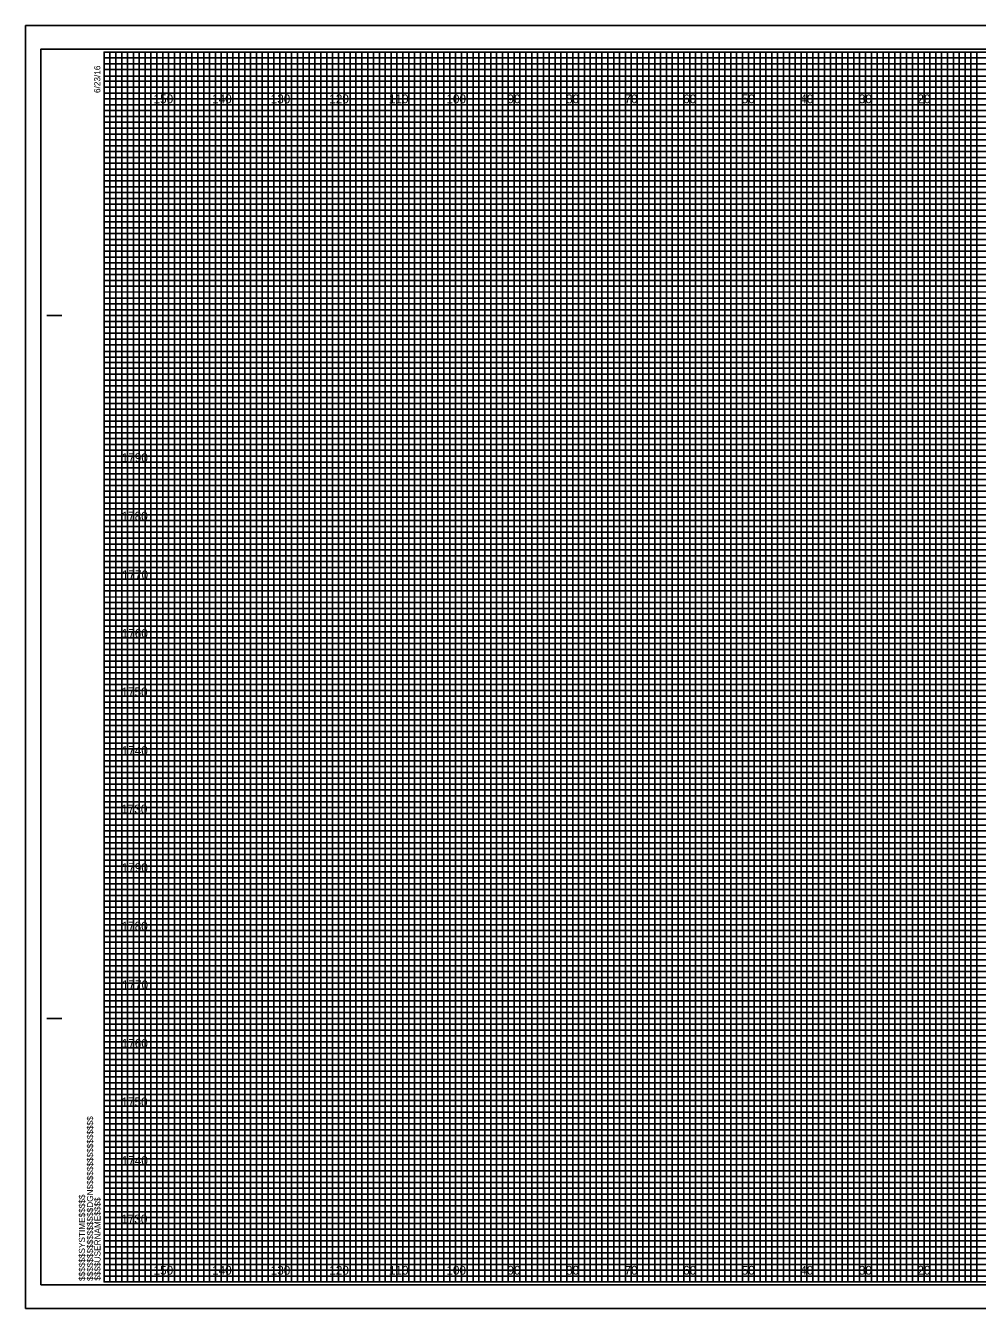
# Model space of a CAD drawing. Extents: x -15 to 323, y -5 to 6170.
# Drawn here: x -13.4 to 149.1, y 3955.5 to 4174.5 of the extents above; entities that cross this region are included whole.
import ezdxf

# ---------------------------------------------------------------- set-up
doc = ezdxf.new("R2010")
doc.units = 0
for name, color, linetype in [('Prop XS DDE', 7, 'Continuous'), ('Prop XS DDE Slope Text', 7, 'Continuous'), ('Prop XS DDE Text', 7, 'Continuous'), ('Prop XS Earthwork Shape', 7, 'Continuous'), ('Prop XS Noise Wall', 7, 'Continuous'), ('Prop XS Retaining Wall', 7, 'Continuous'), ('Prop XS Station Labels', 7, 'Continuous'), ('Scratch_Level_3', 7, 'Continuous'), ('Scratch_Level_7', 7, 'Continuous'), ('Scratch_Level_8', 7, 'Continuous'), ('Sheet Cross Section Grid Minor 1 CELL', 7, 'Continuous')]:
    doc.layers.add(name, color=color, linetype=linetype)

msp = doc.modelspace()

# ---------------------------------------------------------------- linework, layer by layer
at = {"layer": 'Prop XS DDE'}
msp.add_lwpolyline([(-13.4, 3955.5), (323.3, 3955.5), (323.3, 4174.5), (-13.4, 4174.5)], close=True, dxfattribs=at)
at = {"layer": 'Prop XS DDE Slope Text'}
msp.add_lwpolyline([(-10.8, 3959.5), (322.4, 3959.5), (322.4, 4170.5), (-10.8, 4170.5)], close=True, dxfattribs=at)
at = {"layer": 'Prop XS DDE Text'}
for p, q in [((10, 3960), (10, 4170)), ((20, 3960), (20, 4170)), ((30, 3960), (30, 4170)), ((40, 3960), (40, 4170)), ((50, 3960), (50, 4170)), ((60, 3960), (60, 4170)), ((70, 3960), (70, 4170)), ((80, 3960), (80, 4170)), ((90, 3960), (90, 4170)), ((100, 3960), (100, 4170)), ((110, 3960), (110, 4170)), ((120, 3960), (120, 4170)), ((130, 3960), (130, 4170)), ((140, 3960), (140, 4170)), ((0, 4160), (320, 4160)), ((0, 4150), (320, 4150)), ((0, 4140), (320, 4140)), ((0, 4130), (320, 4130)), ((0, 4120), (320, 4120)), ((0, 4110), (320, 4110)), ((0, 4100), (320, 4100)), ((0, 4090), (320, 4090)), ((0, 4080), (320, 4080)), ((0, 4070), (320, 4070)), ((0, 4060), (320, 4060)), ((0, 4050), (320, 4050)), ((0, 4040), (320, 4040)), ((0, 4030), (320, 4030)), ((0, 4020), (320, 4020)), ((0, 4010), (320, 4010)), ((0, 4000), (320, 4000)), ((0, 3990), (320, 3990)), ((0, 3980), (320, 3980)), ((0, 3970), (320, 3970))]:
    msp.add_line(p, q, dxfattribs=at)
at = {"layer": 'Prop XS Earthwork Shape'}
for p, q in [((10, 4170), (0, 4170)), ((10, 3960), (10, 4170)), ((30, 4170), (20, 4170)), ((20, 4170), (20, 3960)), ((30, 3960), (30, 4170)), ((50, 4170), (40, 4170)), ((40, 4170), (40, 3960)), ((50, 3960), (50, 4170)), ((70, 4170), (60, 4170)), ((60, 4170), (60, 3960)), ((70, 3960), (70, 4170)), ((90, 4170), (80, 4170)), ((80, 4170), (80, 3960)), ((90, 3960), (90, 4170)), ((110, 4170), (100, 4170)), ((100, 4170), (100, 3960)), ((110, 3960), (110, 4170)), ((130, 4170), (120, 4170)), ((120, 4170), (120, 3960)), ((130, 3960), (130, 4170)), ((150, 4170), (140, 4170)), ((140, 4170), (140, 3960)), ((20, 3960), (10, 3960)), ((40, 3960), (30, 3960)), ((60, 3960), (50, 3960)), ((80, 3960), (70, 3960)), ((100, 3960), (90, 3960)), ((120, 3960), (110, 3960)), ((140, 3960), (130, 3960))]:
    msp.add_line(p, q, dxfattribs=at)
for points in [[(0, 4160), (320, 4160), (320, 4150), (0, 4150)], [(0, 4140), (320, 4140), (320, 4130), (0, 4130)], [(0, 4120), (320, 4120), (320, 4110), (0, 4110)], [(0, 4100), (320, 4100), (320, 4090), (0, 4090)], [(0, 4080), (320, 4080), (320, 4070), (0, 4070)], [(0, 4060), (320, 4060), (320, 4050), (0, 4050)], [(0, 4040), (320, 4040), (320, 4030), (0, 4030)], [(0, 4020), (320, 4020), (320, 4010), (0, 4010)], [(0, 4000), (320, 4000), (320, 3990), (0, 3990)], [(0, 3980), (320, 3980), (320, 3970), (0, 3970)]]:
    msp.add_lwpolyline(points, dxfattribs=at)
at = {"layer": 'Prop XS Noise Wall'}
for p, q in [((-9.8, 4125), (-7.3, 4125)), ((-9.7, 4125), (-7.2, 4125)), ((-9.8, 4005), (-7.3, 4005)), ((-9.7, 4005), (-7.2, 4005)), ((0, 3960), (0, 3960)), ((0, 3960), (0, 3960)), ((0, 3960), (0, 3960)), ((0, 3960), (0, 3960)), ((0, 3960), (0, 3960)), ((0, 3960), (0, 3960)), ((0, 3960), (0, 3960))]:
    msp.add_line(p, q, dxfattribs=at)
msp.add_lwpolyline([(320, 4170), (0, 4170), (0, 3960), (320, 3960)], close=True, dxfattribs=at)
at = {"layer": 'Prop XS Retaining Wall'}
for points in [[(0, 3960), (1, 3960), (1, 4170), (2, 4170), (2, 3960)], [(2, 3960), (3, 3960), (3, 4170), (4, 4170), (4, 3960)], [(5, 3960), (6, 3960), (6, 4170), (7, 4170), (7, 3960)], [(7, 3960), (8, 3960), (8, 4170), (9, 4170), (9, 3960)], [(10, 3960), (11, 3960), (11, 4170), (12, 4170), (12, 3960)], [(12, 3960), (13, 3960), (13, 4170), (14, 4170), (14, 3960)], [(15, 3960), (16, 3960), (16, 4170), (17, 4170), (17, 3960)], [(17, 3960), (18, 3960), (18, 4170), (19, 4170), (19, 3960)], [(20, 3960), (21, 3960), (21, 4170), (22, 4170), (22, 3960)], [(22, 3960), (23, 3960), (23, 4170), (24, 4170), (24, 3960)], [(25, 3960), (26, 3960), (26, 4170), (27, 4170), (27, 3960)], [(27, 3960), (28, 3960), (28, 4170), (29, 4170), (29, 3960)], [(30, 3960), (31, 3960), (31, 4170), (32, 4170), (32, 3960)], [(32, 3960), (33, 3960), (33, 4170), (34, 4170), (34, 3960)], [(35, 3960), (36, 3960), (36, 4170), (37, 4170), (37, 3960)], [(37, 3960), (38, 3960), (38, 4170), (39, 4170), (39, 3960)], [(40, 3960), (41, 3960), (41, 4170), (42, 4170), (42, 3960)], [(42, 3960), (43, 3960), (43, 4170), (44, 4170), (44, 3960)], [(45, 3960), (46, 3960), (46, 4170), (47, 4170), (47, 3960)], [(47, 3960), (48, 3960), (48, 4170), (49, 4170), (49, 3960)], [(50, 3960), (51, 3960), (51, 4170), (52, 4170), (52, 3960)], [(52, 3960), (53, 3960), (53, 4170), (54, 4170), (54, 3960)], [(55, 3960), (56, 3960), (56, 4170), (57, 4170), (57, 3960)], [(57, 3960), (58, 3960), (58, 4170), (59, 4170), (59, 3960)], [(60, 3960), (61, 3960), (61, 4170), (62, 4170), (62, 3960)], [(62, 3960), (63, 3960), (63, 4170), (64, 4170), (64, 3960)], [(65, 3960), (66, 3960), (66, 4170), (67, 4170), (67, 3960)], [(67, 3960), (68, 3960), (68, 4170), (69, 4170), (69, 3960)], [(70, 3960), (71, 3960), (71, 4170), (72, 4170), (72, 3960)], [(72, 3960), (73, 3960), (73, 4170), (74, 4170), (74, 3960)], [(75, 3960), (76, 3960), (76, 4170), (77, 4170), (77, 3960)], [(77, 3960), (78, 3960), (78, 4170), (79, 4170), (79, 3960)], [(80, 3960), (81, 3960), (81, 4170), (82, 4170), (82, 3960)], [(82, 3960), (83, 3960), (83, 4170), (84, 4170), (84, 3960)], [(85, 3960), (86, 3960), (86, 4170), (87, 4170), (87, 3960)], [(87, 3960), (88, 3960), (88, 4170), (89, 4170), (89, 3960)], [(90, 3960), (91, 3960), (91, 4170), (92, 4170), (92, 3960)], [(92, 3960), (93, 3960), (93, 4170), (94, 4170), (94, 3960)], [(95, 3960), (96, 3960), (96, 4170), (97, 4170), (97, 3960)], [(97, 3960), (98, 3960), (98, 4170), (99, 4170), (99, 3960)], [(100, 3960), (101, 3960), (101, 4170), (102, 4170), (102, 3960)], [(102, 3960), (103, 3960), (103, 4170), (104, 4170), (104, 3960)], [(105, 3960), (106, 3960), (106, 4170), (107, 4170), (107, 3960)], [(107, 3960), (108, 3960), (108, 4170), (109, 4170), (109, 3960)], [(110, 3960), (111, 3960), (111, 4170), (112, 4170), (112, 3960)], [(112, 3960), (113, 3960), (113, 4170), (114, 4170), (114, 3960)], [(115, 3960), (116, 3960), (116, 4170), (117, 4170), (117, 3960)], [(117, 3960), (118, 3960), (118, 4170), (119, 4170), (119, 3960)], [(120, 3960), (121, 3960), (121, 4170), (122, 4170), (122, 3960)], [(122, 3960), (123, 3960), (123, 4170), (124, 4170), (124, 3960)], [(125, 3960), (126, 3960), (126, 4170), (127, 4170), (127, 3960)], [(127, 3960), (128, 3960), (128, 4170), (129, 4170), (129, 3960)], [(130, 3960), (131, 3960), (131, 4170), (132, 4170), (132, 3960)], [(132, 3960), (133, 3960), (133, 4170), (134, 4170), (134, 3960)], [(135, 3960), (136, 3960), (136, 4170), (137, 4170), (137, 3960)], [(137, 3960), (138, 3960), (138, 4170), (139, 4170), (139, 3960)], [(140, 3960), (141, 3960), (141, 4170), (142, 4170), (142, 3960)], [(142, 3960), (143, 3960), (143, 4170), (144, 4170), (144, 3960)], [(145, 3960), (146, 3960), (146, 4170), (147, 4170), (147, 3960)], [(147, 3960), (148, 3960), (148, 4170), (149, 4170), (149, 3960)]]:
    msp.add_lwpolyline(points, dxfattribs=at)
at = {"layer": 'Prop XS Station Labels'}
for points in [[(0, 4170), (5, 4170), (5, 3960), (15, 3960), (15, 4170), (25, 4170), (25, 3960), (35, 3960), (35, 4170), (45, 4170), (45, 3960), (55, 3960), (55, 4170), (65, 4170), (65, 3960), (75, 3960), (75, 4170), (85, 4170), (85, 3960), (95, 3960), (95, 4170), (105, 4170), (105, 3960), (115, 3960), (115, 4170), (125, 4170), (125, 3960), (135, 3960), (135, 4170), (145, 4170), (145, 3960), (155, 3960)], [(0, 4165), (275, 4165)], [(0, 4145), (320, 4145), (320, 4155), (0, 4155)], [(0, 4125), (320, 4125), (320, 4135), (0, 4135)], [(0, 4105), (320, 4105), (320, 4115), (0, 4115)], [(0, 4085), (320, 4085), (320, 4095), (0, 4095)], [(0, 4065), (320, 4065), (320, 4075), (0, 4075)], [(0, 4045), (320, 4045), (320, 4055), (0, 4055)], [(0, 4025), (320, 4025), (320, 4035), (0, 4035)], [(0, 4005), (320, 4005), (320, 4015), (0, 4015)], [(0, 3985), (320, 3985), (320, 3995), (0, 3995)], [(0, 3965), (320, 3965), (320, 3975), (0, 3975)]]:
    msp.add_lwpolyline(points, dxfattribs=at)
at = {"layer": 'Scratch_Level_7'}
for p, q in [((323.3, 4174.5), (-13.4, 4174.5)), ((-13.4, 4174.5), (-13.4, 3955.5)), ((-13.4, 3955.5), (323.3, 3955.5))]:
    msp.add_line(p, q, dxfattribs=at)
at = {"layer": 'Sheet Cross Section Grid Minor 1 CELL'}
for p, q in [((0, 4169), (260, 4169)), ((260, 4167.98), (0, 4167.98)), ((0, 4167.98), (0, 4167)), ((0, 4167), (260, 4167)), ((260, 4165.89), (0, 4165.89)), ((0, 4165.89), (0, 4164)), ((0, 4164), (320, 4164))]:
    msp.add_line(p, q, dxfattribs=at)
for points in [[(0, 4163), (270, 4163), (320, 4163), (320, 4162), (0, 4162)], [(0, 4161), (320, 4161), (320, 4159), (0, 4159)], [(0, 4158), (320, 4158), (320, 4157), (0, 4156.98)], [(0, 4156), (320, 4156), (320, 4154), (0, 4154)], [(0, 4153), (320, 4153), (320, 4152), (0, 4152)], [(0, 4151), (320, 4151), (320, 4149), (0, 4149)], [(0, 4148), (320, 4148), (320, 4147), (0, 4147)], [(0, 4146), (320, 4146), (320, 4144), (0, 4144)], [(0, 4143), (320, 4143), (320, 4142), (0, 4142)], [(0, 4141), (320, 4141), (320, 4139), (0, 4139)], [(0, 4138), (320, 4138), (320, 4137), (0, 4137)], [(0, 4136), (320, 4136), (320, 4133.95), (320, 4133), (320, 4132), (0, 4132)], [(0, 4134), (320, 4134), (320, 4133), (0, 4133)], [(0, 4131), (320, 4131), (320, 4129), (0, 4129.03)], [(0, 4129.03), (320, 4129), (320, 4128), (0, 4128)], [(0, 4127), (320, 4127), (320, 4126), (0, 4126)], [(0, 4124), (320, 4124), (320, 4123), (0, 4123)], [(0, 4122), (320, 4122), (320, 4121), (0, 4121)], [(-0.07, 4118.89), (320, 4118.89), (320, 4117.88), (-0.07, 4117.88)], [(0, 4117), (320, 4117), (320, 4116), (0, 4116)], [(0, 4114), (320, 4114), (320, 4113), (0, 4113)], [(0, 4112), (320, 4112), (320, 4111), (0, 4111)], [(0, 4109), (320, 4109), (320, 4108), (0, 4108)], [(0, 4107), (320, 4107), (320, 4106), (0, 4106)], [(0, 4104), (320, 4104), (320, 4103), (0, 4103)], [(0, 4102), (320, 4102), (320, 4101), (0, 4101)], [(0, 4099), (320, 4099), (319.99, 4097.98), (0, 4098)], [(0, 4097), (320, 4097), (320, 4096), (0, 4096)], [(0, 4094), (320, 4094), (320, 4093), (0, 4093)], [(0, 4092), (320, 4092), (320, 4091), (0, 4091)], [(0, 4089), (320, 4089), (320, 4088), (0, 4088)], [(0, 4087), (320, 4087), (320, 4086), (0, 4086)], [(0, 4084), (320, 4084), (320, 4083), (0, 4083)], [(0, 4082), (320, 4082), (320, 4081), (0, 4081)], [(0, 4079), (320, 4079), (320, 4078), (0, 4078)], [(0, 4076.99), (320.07, 4076.91), (320, 4076), (0, 4076)], [(0, 4074), (320, 4074), (320, 4073), (0, 4073)], [(0, 4072), (320, 4072), (320, 4071), (0, 4071)], [(0, 4069), (320, 4069), (320, 4068), (0, 4068)], [(0, 4067), (320, 4067), (320, 4066), (0, 4066)], [(0, 4064), (320, 4064), (320, 4063), (0, 4063)], [(0, 4062), (320, 4062), (320, 4061), (0, 4061)], [(0, 4059), (320, 4059), (320, 4058), (0, 4058)], [(0, 4057), (320, 4057), (320, 4056), (0, 4056)], [(0, 4054), (320, 4054), (320, 4053), (0, 4053)], [(0, 4052), (320, 4052), (320, 4051), (0, 4051)], [(0, 4049), (320, 4049), (320, 4048), (0, 4048)], [(0, 4047), (320, 4047), (320, 4046), (0, 4046)], [(0, 4044), (320, 4044), (320, 4043), (0, 4043)], [(0, 4042), (320, 4042), (320, 4041), (0, 4041)], [(0, 4039), (320, 4039), (319.99, 4037.98), (0, 4038)], [(0, 4037), (320, 4037), (320, 4036), (0, 4036)], [(0, 4034), (320, 4034), (320, 4033), (0, 4033)], [(0, 4032), (320, 4032), (320, 4031), (0, 4031)], [(0, 4029), (320, 4029), (320, 4028), (0, 4028)], [(0, 4027), (320, 4027), (320, 4026), (0, 4026)], [(0, 4024), (320, 4024), (320, 4023), (0, 4023)], [(0, 4022), (320, 4022), (320, 4021), (0, 4021)], [(0, 4019), (320, 4019), (320, 4018), (0, 4018)], [(0, 4016.99), (320.07, 4016.91), (320, 4016), (0, 4016)], [(0, 4014), (320, 4014), (320, 4013), (0, 4013)], [(0, 4012), (320, 4012), (320, 4011), (0, 4011)], [(0, 4009), (320, 4009), (320, 4008), (0, 4008)], [(0, 4007), (320, 4007), (320, 4006), (0, 4006)], [(0, 4004), (320, 4004), (320, 4003), (0, 4003)], [(0, 4002), (320, 4002), (320, 4001), (0, 4001)], [(0, 3999), (320, 3999), (320, 3998), (0, 3998)], [(0, 3997), (320, 3997), (320, 3996), (0, 3996)], [(0, 3994), (320, 3994), (320, 3993), (0, 3993)], [(0, 3992), (320, 3992), (320, 3991), (0, 3991)], [(0, 3989), (320, 3989), (320, 3988), (0, 3988)], [(0, 3987), (320, 3987), (320, 3986), (0, 3986)], [(0, 3984), (320, 3984), (320, 3983), (0, 3983)], [(0, 3982), (320, 3982), (320, 3981), (0, 3981)], [(0, 3979), (320, 3979), (320, 3978), (0, 3978)], [(0, 3977), (320, 3977), (320, 3976), (0, 3976)], [(0, 3974), (320, 3974), (320, 3973), (0, 3973)], [(0, 3972), (320, 3972), (320, 3971), (0, 3971)], [(0, 3969), (320, 3969), (320, 3968), (0, 3968)], [(0, 3967), (320, 3967), (320, 3966), (0, 3966)], [(0, 3964), (320, 3964), (320, 3963), (0, 3963)], [(0, 3962), (320, 3962), (320, 3961), (0, 3961)]]:
    msp.add_lwpolyline(points, dxfattribs=at)

# ---------------------------------------------------------------- texts
at = {"layer": 'Prop XS Noise Wall'}
for s, p in [('6/23/16', (-0.65, 4163)), ('$$$$$$$$$$$$$$$$DGN$$$$$$$$$$$$$$$$', (-1.88, 3960.18)), ('$$$$$$SYSTIME$$$$$', (-3.26, 3960.18)), ('$$$$USERNAME$$$$', (-0.62, 3960.23))]:
    msp.add_text(s, height=1.05, rotation=90, dxfattribs=at).set_placement(p)
at = {"layer": 'Scratch_Level_3'}
for s, p in [('1790', (3, 4100)), ('1780', (2.98, 4090)), ('1770', (3.04, 4080)), ('1760', (3, 4070)), ('1750', (2.96, 4060)), ('1740', (3, 4050)), ('1730', (2.92, 4040)), ('1790', (3, 4030)), ('1780', (2.98, 4020)), ('1770', (3.04, 4010)), ('1760', (3, 4000)), ('1750', (2.96, 3990)), ('1740', (3, 3980)), ('1730', (2.92, 3970))]:
    msp.add_text(s, height=1.5, dxfattribs=at).set_placement(p)
at = {"layer": 'Scratch_Level_8'}
for s, p in [('150', (8.44, 4161.25)), ('140', (18.44, 4161.25)), ('130', (28.44, 4161.25)), ('120', (38.44, 4161.25)), ('110', (48.62, 4161.25)), ('100', (58.44, 4161.25)), ('90', (68.86, 4161.25)), ('80', (78.86, 4161.25)), ('70', (88.86, 4161.25)), ('60', (98.86, 4161.25)), ('50', (108.86, 4161.25)), ('40', (118.86, 4161.25)), ('30', (128.86, 4161.25)), ('20', (138.86, 4161.25)), ('150', (8.44, 3961.25)), ('140', (18.44, 3961.25)), ('130', (28.44, 3961.25)), ('120', (38.44, 3961.25)), ('110', (48.62, 3961.25)), ('100', (58.44, 3961.25)), ('90', (68.86, 3961.25)), ('80', (78.86, 3961.25)), ('70', (88.86, 3961.25)), ('60', (98.86, 3961.25)), ('50', (108.86, 3961.25)), ('40', (118.86, 3961.25)), ('30', (128.86, 3961.25)), ('20', (138.86, 3961.25))]:
    msp.add_text(s, height=1.5, dxfattribs=at).set_placement(p)

doc.saveas('drawing.dxf')
